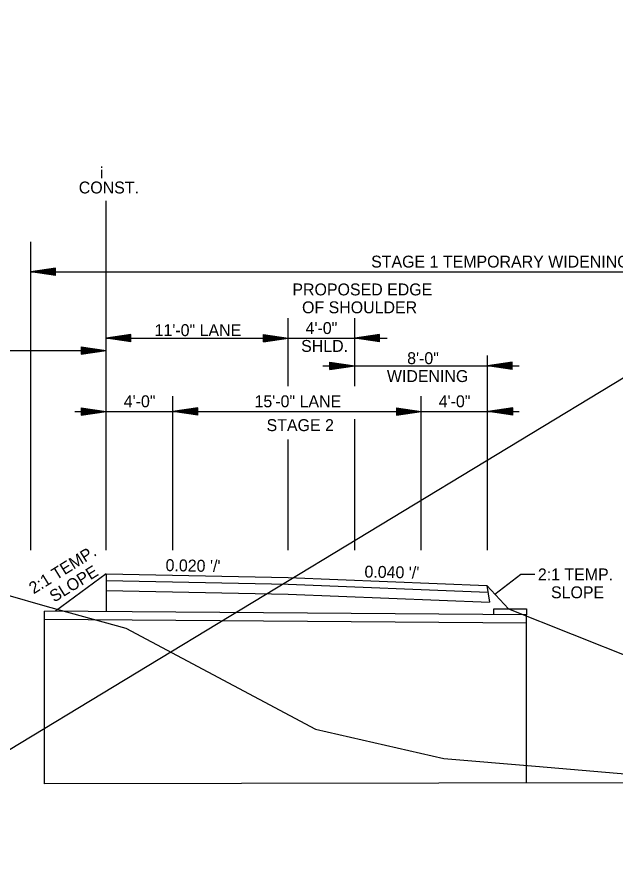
# Model space of a CAD drawing. Extents: x 1807779 to 1818251, y 673292 to 678849.
# Drawn here: x 1815350 to 1815712, y 673775 to 674291 of the extents above; entities that cross this region are included whole.
import ezdxf

# ---------------------------------------------------------------- set-up
doc = ezdxf.new("R2010")
doc.units = 0
for name, color, linetype in [('Default', 7, 'Continuous'), ('Dimensions', 7, 'Continuous'), ('S_PHOTO_CTL_ANNOT', 7, 'Continuous'), ('T_Drafting', 7, 'Continuous')]:
    doc.layers.add(name, color=color, linetype=linetype)

msp = doc.modelspace()

# ---------------------------------------------------------------- linework, layer by layer
at = {"layer": 'Default'}
for p, q in [((1815403.54, 673955.01), (1815372.92, 673932.44)), ((1815403.54, 673955.01), (1815403.54, 673932.21)), ((1815633.54, 673948.01), (1815646.7, 673933.98)), ((1815633.54, 673948.01), (1815635.21, 673937.94)), ((1815646.7, 673933.98), (1815908.79, 673829.19)), ((1815657.47, 673930.26), (1815366.21, 673932.49)), ((1815366.21, 673828.16), (1815366.21, 673932.46)), ((1815657.47, 673828.86), (1815657.47, 673930.26)), ((1815657.47, 673925.26), (1815366.21, 673927.49)), ((1815941.77, 673829.26), (1815366.21, 673828.16))]:
    msp.add_line(p, q, dxfattribs=at)
for points in [[(1815403.54, 673955.01), (1815513.54, 673952.81), (1815633.54, 673948.01)], [(1815403.54, 673951.1), (1815513.54, 673948.9), (1815634.19, 673944.08)], [(1815403.54, 673945.01), (1815513.54, 673942.81), (1815635.21, 673937.94)], [(1815637.9, 673930.23), (1815637.9, 673933.98), (1815657.47, 673933.98), (1815657.47, 673930.26)]]:
    msp.add_lwpolyline(points, dxfattribs=at)
at = {"layer": 'Dimensions'}
for p, q in [((1815403.54, 673969.32), (1815403.54, 674180.49)), ((1815358.01, 673969.32), (1815358.01, 674155.59)), ((1815373.01, 674139.79), (1815358.01, 674137.54)), ((1815358.01, 674137.54), (1815931.56, 674137.54)), ((1815373.01, 674135.29), (1815358.01, 674137.54)), ((1815373.01, 674139.41), (1815360.52, 674137.54)), ((1815373.01, 674135.66), (1815360.52, 674137.54)), ((1815373.01, 674139.03), (1815363.1, 674137.54)), ((1815373.01, 674136.05), (1815363.1, 674137.54)), ((1815373.01, 674138.66), (1815365.59, 674137.54)), ((1815373.01, 674136.42), (1815365.59, 674137.54)), ((1815373.01, 674138.27), (1815368.14, 674137.54)), ((1815373.01, 674136.81), (1815368.14, 674137.54)), ((1815373.01, 674137.89), (1815370.64, 674137.54)), ((1815373.01, 674137.19), (1815370.64, 674137.54)), ((1815373.01, 674135.29), (1815373.01, 674139.79)), ((1815513.54, 674068.48), (1815513.54, 674109.57)), ((1815553.77, 674068.48), (1815553.77, 674109.57)), ((1815418.54, 674099.65), (1815403.54, 674097.4)), ((1815418.54, 674099.28), (1815406.05, 674097.4)), ((1815418.54, 674095.15), (1815418.54, 674099.65)), ((1815498.54, 674099.65), (1815513.54, 674097.4)), ((1815498.54, 674095.15), (1815498.54, 674099.65)), ((1815498.54, 674099.28), (1815511.04, 674097.4)), ((1815568.77, 674099.65), (1815553.77, 674097.4)), ((1815568.77, 674099.28), (1815556.28, 674097.4)), ((1815568.77, 674095.15), (1815568.77, 674099.65)), ((1815403.54, 674097.4), (1815462.97, 674097.4)), ((1815403.54, 674097.4), (1815513.54, 674097.4)), ((1815418.54, 674095.15), (1815403.54, 674097.4)), ((1815418.54, 674095.53), (1815406.05, 674097.4)), ((1815418.54, 674098.89), (1815408.63, 674097.4)), ((1815418.54, 674095.91), (1815408.63, 674097.4)), ((1815418.54, 674098.52), (1815411.12, 674097.4)), ((1815418.54, 674096.28), (1815411.12, 674097.4)), ((1815418.54, 674098.14), (1815413.67, 674097.4)), ((1815418.54, 674096.67), (1815413.67, 674097.4)), ((1815418.54, 674097.75), (1815416.17, 674097.4)), ((1815418.54, 674097.05), (1815416.17, 674097.4)), ((1815498.54, 674098.89), (1815508.46, 674097.4)), ((1815498.54, 674098.52), (1815505.96, 674097.4)), ((1815498.54, 674098.14), (1815503.42, 674097.4)), ((1815498.54, 674097.75), (1815500.91, 674097.4)), ((1815498.54, 674095.15), (1815513.54, 674097.4)), ((1815498.54, 674096.67), (1815503.42, 674097.4)), ((1815498.54, 674095.91), (1815508.46, 674097.4)), ((1815498.54, 674095.53), (1815511.04, 674097.4)), ((1815498.54, 674096.28), (1815505.96, 674097.4)), ((1815498.54, 674097.05), (1815500.91, 674097.4)), ((1815513.54, 674097.4), (1815573.41, 674097.4)), ((1815568.77, 674095.15), (1815553.77, 674097.4)), ((1815568.77, 674095.53), (1815556.28, 674097.4)), ((1815568.77, 674098.89), (1815558.86, 674097.4)), ((1815568.77, 674095.91), (1815558.86, 674097.4)), ((1815568.77, 674098.52), (1815561.36, 674097.4)), ((1815568.77, 674096.28), (1815561.36, 674097.4)), ((1815568.77, 674098.14), (1815563.9, 674097.4)), ((1815568.77, 674096.67), (1815563.9, 674097.4)), ((1815568.77, 674097.75), (1815566.4, 674097.4)), ((1815568.77, 674097.05), (1815566.4, 674097.4)), ((1815105.79, 674090.01), (1815403.54, 674090.02)), ((1815388.54, 674092.27), (1815403.54, 674090.02)), ((1815388.54, 674092.27), (1815388.54, 674087.77)), ((1815388.54, 674091.89), (1815401.04, 674090.02)), ((1815388.54, 674091.51), (1815398.46, 674090.02)), ((1815388.54, 674091.13), (1815395.96, 674090.02)), ((1815388.54, 674090.74), (1815393.42, 674090.02)), ((1815388.54, 674090.37), (1815390.91, 674090.02)), ((1815388.54, 674087.77), (1815403.54, 674090.02)), ((1815388.54, 674089.28), (1815393.42, 674090.02)), ((1815388.54, 674088.52), (1815398.46, 674090.02)), ((1815388.54, 674088.14), (1815401.04, 674090.02)), ((1815388.54, 674088.9), (1815395.96, 674090.02)), ((1815388.54, 674089.66), (1815390.91, 674090.02)), ((1815633.92, 673969.32), (1815633.92, 674086.91)), ((1815534.57, 674080.7), (1815653.17, 674080.7)), ((1815538.77, 674082.95), (1815553.77, 674080.7)), ((1815538.77, 674078.45), (1815538.77, 674082.95)), ((1815538.77, 674082.58), (1815551.27, 674080.7)), ((1815538.77, 674082.2), (1815548.69, 674080.7)), ((1815538.77, 674081.82), (1815546.19, 674080.7)), ((1815538.77, 674081.44), (1815543.65, 674080.7)), ((1815538.77, 674081.06), (1815541.14, 674080.7)), ((1815538.77, 674078.45), (1815553.77, 674080.7)), ((1815538.77, 674079.98), (1815543.65, 674080.7)), ((1815538.77, 674079.21), (1815548.69, 674080.7)), ((1815538.77, 674078.83), (1815551.27, 674080.7)), ((1815538.77, 674079.59), (1815546.19, 674080.7)), ((1815538.77, 674080.35), (1815541.14, 674080.7)), ((1815648.92, 674082.95), (1815633.92, 674080.7)), ((1815648.92, 674078.45), (1815633.92, 674080.7)), ((1815648.92, 674082.58), (1815636.43, 674080.7)), ((1815648.92, 674078.83), (1815636.43, 674080.7)), ((1815648.92, 674082.2), (1815639.01, 674080.7)), ((1815648.92, 674079.21), (1815639.01, 674080.7)), ((1815648.92, 674081.82), (1815641.51, 674080.7)), ((1815648.92, 674079.59), (1815641.51, 674080.7)), ((1815648.92, 674081.44), (1815644.05, 674080.7)), ((1815648.92, 674079.98), (1815644.05, 674080.7)), ((1815648.92, 674081.06), (1815646.55, 674080.7)), ((1815648.92, 674080.35), (1815646.55, 674080.7)), ((1815648.92, 674078.45), (1815648.92, 674082.95)), ((1815443.92, 673969.32), (1815443.92, 674062.37)), ((1815593.92, 673969.32), (1815593.92, 674062.37)), ((1815384.68, 674053.16), (1815443.92, 674053.16)), ((1815388.54, 674055.41), (1815403.54, 674053.16)), ((1815388.54, 674055.41), (1815388.54, 674050.91)), ((1815388.54, 674055.03), (1815401.04, 674053.16)), ((1815388.54, 674054.65), (1815398.46, 674053.16)), ((1815388.54, 674054.28), (1815395.96, 674053.16)), ((1815388.54, 674053.89), (1815393.42, 674053.16)), ((1815388.54, 674053.51), (1815390.91, 674053.16)), ((1815388.54, 674050.91), (1815403.54, 674053.16)), ((1815388.54, 674052.42), (1815393.42, 674053.16)), ((1815388.54, 674051.67), (1815398.46, 674053.16)), ((1815388.54, 674051.28), (1815401.04, 674053.16)), ((1815388.54, 674052.04), (1815395.96, 674053.16)), ((1815388.54, 674052.81), (1815390.91, 674053.16)), ((1815458.92, 674055.41), (1815443.92, 674053.16)), ((1815443.92, 674053.16), (1815593.92, 674053.16)), ((1815458.92, 674050.91), (1815443.92, 674053.16)), ((1815458.92, 674055.03), (1815446.43, 674053.16)), ((1815458.92, 674051.28), (1815446.43, 674053.16)), ((1815458.92, 674054.65), (1815449.01, 674053.16)), ((1815458.92, 674051.67), (1815449.01, 674053.16)), ((1815458.92, 674054.28), (1815451.51, 674053.16)), ((1815458.92, 674052.04), (1815451.51, 674053.16)), ((1815458.92, 674053.89), (1815454.05, 674053.16)), ((1815458.92, 674052.43), (1815454.05, 674053.16)), ((1815458.92, 674053.51), (1815456.55, 674053.16)), ((1815458.92, 674052.81), (1815456.55, 674053.16)), ((1815458.92, 674050.91), (1815458.92, 674055.41)), ((1815578.92, 674055.41), (1815593.92, 674053.16)), ((1815578.92, 674055.41), (1815578.92, 674050.91)), ((1815578.92, 674055.03), (1815591.42, 674053.16)), ((1815578.92, 674054.65), (1815588.84, 674053.16)), ((1815578.92, 674054.28), (1815586.34, 674053.16)), ((1815578.92, 674053.89), (1815583.8, 674053.16)), ((1815578.92, 674053.51), (1815581.29, 674053.16)), ((1815578.92, 674050.91), (1815593.92, 674053.16)), ((1815578.92, 674052.42), (1815583.8, 674053.16)), ((1815578.92, 674051.67), (1815588.84, 674053.16)), ((1815578.92, 674051.28), (1815591.42, 674053.16)), ((1815578.92, 674052.04), (1815586.34, 674053.16)), ((1815578.92, 674052.81), (1815581.29, 674053.16)), ((1815593.92, 674053.16), (1815653.17, 674053.16)), ((1815649.31, 674055.41), (1815634.31, 674053.16)), ((1815649.31, 674050.91), (1815634.31, 674053.16)), ((1815649.31, 674055.03), (1815636.81, 674053.16)), ((1815649.31, 674051.28), (1815636.81, 674053.16)), ((1815649.31, 674054.65), (1815639.39, 674053.16)), ((1815649.31, 674051.67), (1815639.39, 674053.16)), ((1815649.31, 674054.28), (1815641.89, 674053.16)), ((1815649.31, 674052.04), (1815641.89, 674053.16)), ((1815649.31, 674053.89), (1815644.43, 674053.16)), ((1815649.31, 674052.43), (1815644.43, 674053.16)), ((1815649.31, 674053.51), (1815646.94, 674053.16)), ((1815649.31, 674052.81), (1815646.94, 674053.16)), ((1815649.31, 674050.91), (1815649.31, 674055.41)), ((1815553.77, 673969.32), (1815553.77, 674048.47)), ((1815513.54, 673969.32), (1815513.54, 674036.24))]:
    msp.add_line(p, q, dxfattribs=at)
msp.add_lwpolyline([(1815638.44, 673942.79), (1815654.14, 673954.87), (1815662.63, 673954.87)], dxfattribs=at)
at = {"layer": 'S_PHOTO_CTL_ANNOT'}
msp.add_line((1814425.79, 673292.32), (1816075.79, 674291.38), dxfattribs=at)
msp.add_lwpolyline([(1815403.54, 673955.01), (1815513.54, 673952.81), (1815633.54, 673948.01)], dxfattribs=at)
at = {"layer": 'T_Drafting'}
msp.add_lwpolyline([(1814480.16, 673949.87), (1814535.82, 673916.91), (1814671.2, 673824.11), (1814833.77, 673936.36), (1814875.27, 673943.12), (1814925.5, 673953.52), (1815020.37, 673955.18), (1815100.55, 673956.25), (1815260.54, 673954.11), (1815289.01, 673953.47), (1815317.34, 673949.88), (1815367.9, 673935.45), (1815415.36, 673922.36), (1815530.07, 673861.35), (1815607.52, 673843.51), (1815663.01, 673838.86), (1815719.46, 673834.02), (1815906.27, 673833.05), (1815973.94, 673835.62)], dxfattribs=at)

# ---------------------------------------------------------------- texts
at = {"layer": 'Dimensions'}
for s, p in [('¡', (1815399.25, 674195.65)), ('CONST.', (1815387.01, 674184.85)), ('STAGE 1 TEMPORARY WIDENING CONSTRUCTION', (1815563.67, 674140.09)), ('PROPOSED EDGE ', (1815516.09, 674123.27)), ('OF SHOULDER', (1815521.92, 674112.47)), ('11\'-0" LANE', (1815432.83, 674098.69)), ('4\'-0" ', (1815524.06, 674099.95)), ('SHLD. ', (1815521.37, 674089.15)), ('8\'-0" ', (1815585.43, 674081.75)), ('WIDENING', (1815573.2, 674070.95)), ('4\'-0"', (1815414.2, 674055.71)), ('15\'-0" LANE', (1815493.21, 674055.71)), ('4\'-0"', (1815604.51, 674055.71)), ('STAGE 2', (1815500.5, 674041.31)), ('2:1 TEMP. ', (1815664.41, 673951.12)), ('SLOPE', (1815672.35, 673940.32))]:
    msp.add_text(s, height=7.2, dxfattribs=at).set_placement(p)
for s, rotation, p in [('2:1 TEMP. ', 31.7342, (1815359.73, 673942.66)), ('SLOPE', 31.7342, (1815372.17, 673937.65)), ("0.020 '/'", 358.8777, (1815439.41, 673956.78)), ("0.040 '/'", 358.8777, (1815559.58, 673952.85))]:
    msp.add_text(s, height=7.2, rotation=rotation, dxfattribs=at).set_placement(p)

doc.saveas('drawing.dxf')
